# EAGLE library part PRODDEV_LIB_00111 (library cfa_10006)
CFAG19264-TMI-TN, 192x64 LCD Module
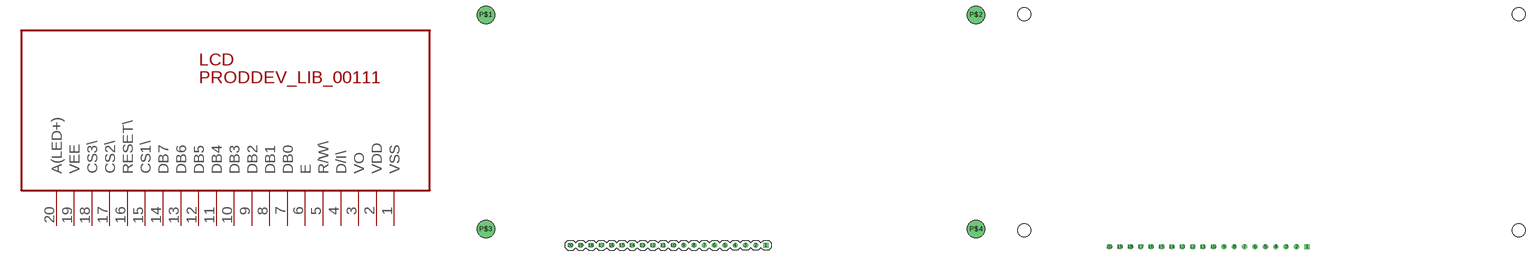
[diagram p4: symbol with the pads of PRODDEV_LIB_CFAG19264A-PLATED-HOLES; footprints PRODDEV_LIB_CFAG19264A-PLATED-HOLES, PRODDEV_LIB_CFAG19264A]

Designator prefix LCD

## PRODDEV_LIB_00111  [PRODDEV_LIB_CFAG19264A-PLATED-HOLES]
1  VSS  pwr
2  VDD  pwr
3  VO  pas
4  D/I\  in
5  R/W\  in
6  E  in
7  DB0
8  DB1
9  DB2
10  DB3
11  DB4
12  DB5
13  DB6
14  DB7
15  CS1\  in
16  RESET\  in
17  CS2\  in
18  CS3\  in
19  VEE  pas
20  A(LED+)  in

## PRODDEV_LIB_00111NON-PLATED-HOLES  [PRODDEV_LIB_CFAG19264A]
Pads as for PRODDEV_LIB_CFAG19264A-PLATED-HOLES

## Footprint PRODDEV_LIB_CFAG19264A-PLATED-HOLES (pad centres in mm)
drill 0.8 square: 1 48.26,0
drill 0.8 round: 2 45.72,0; 3 43.18,0; 4 40.64,0; 5 38.1,0; 6 35.56,0; 7 33.02,0; 8 30.48,0; 9 27.94,0; 10 25.4,0; 11 22.86,0; 12 20.32,0; 13 17.78,0; 14 15.24,0; 15 12.7,0; 16 10.16,0; 17 7.62,0; 18 5.08,0; 19 2.54,0; 20 0,0
drill 3.1 round: P$1 -20.9,57; P$2 100.1,57; P$3 -20.9,4; P$4 100.1,4

## Footprint PRODDEV_LIB_CFAG19264A (pad centres in mm)
drill 0.8 square: 1 48.26,0
drill 0.8 round: 2 45.72,0; 3 43.18,0; 4 40.64,0; 5 38.1,0; 6 35.56,0; 7 33.02,0; 8 30.48,0; 9 27.94,0; 10 25.4,0; 11 22.86,0; 12 20.32,0; 13 17.78,0; 14 15.24,0; 15 12.7,0; 16 10.16,0; 17 7.62,0; 18 5.08,0; 19 2.54,0; 20 0,0
hole 3.2 at -20.9,4
hole 3.2 at 100.1,57
hole 3.2 at -20.9,57
hole 3.2 at 100.1,4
